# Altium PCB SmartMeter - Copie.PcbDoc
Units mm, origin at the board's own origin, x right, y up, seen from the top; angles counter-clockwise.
Board outline 36.42 x 43 mm, 2 copper layers (Top Layer, Bottom Layer), stack 0.071 mm thick; 33 components, 26 nets, 131 pads, 0 vias.
Unrouted connection lines stored in the file: 32.
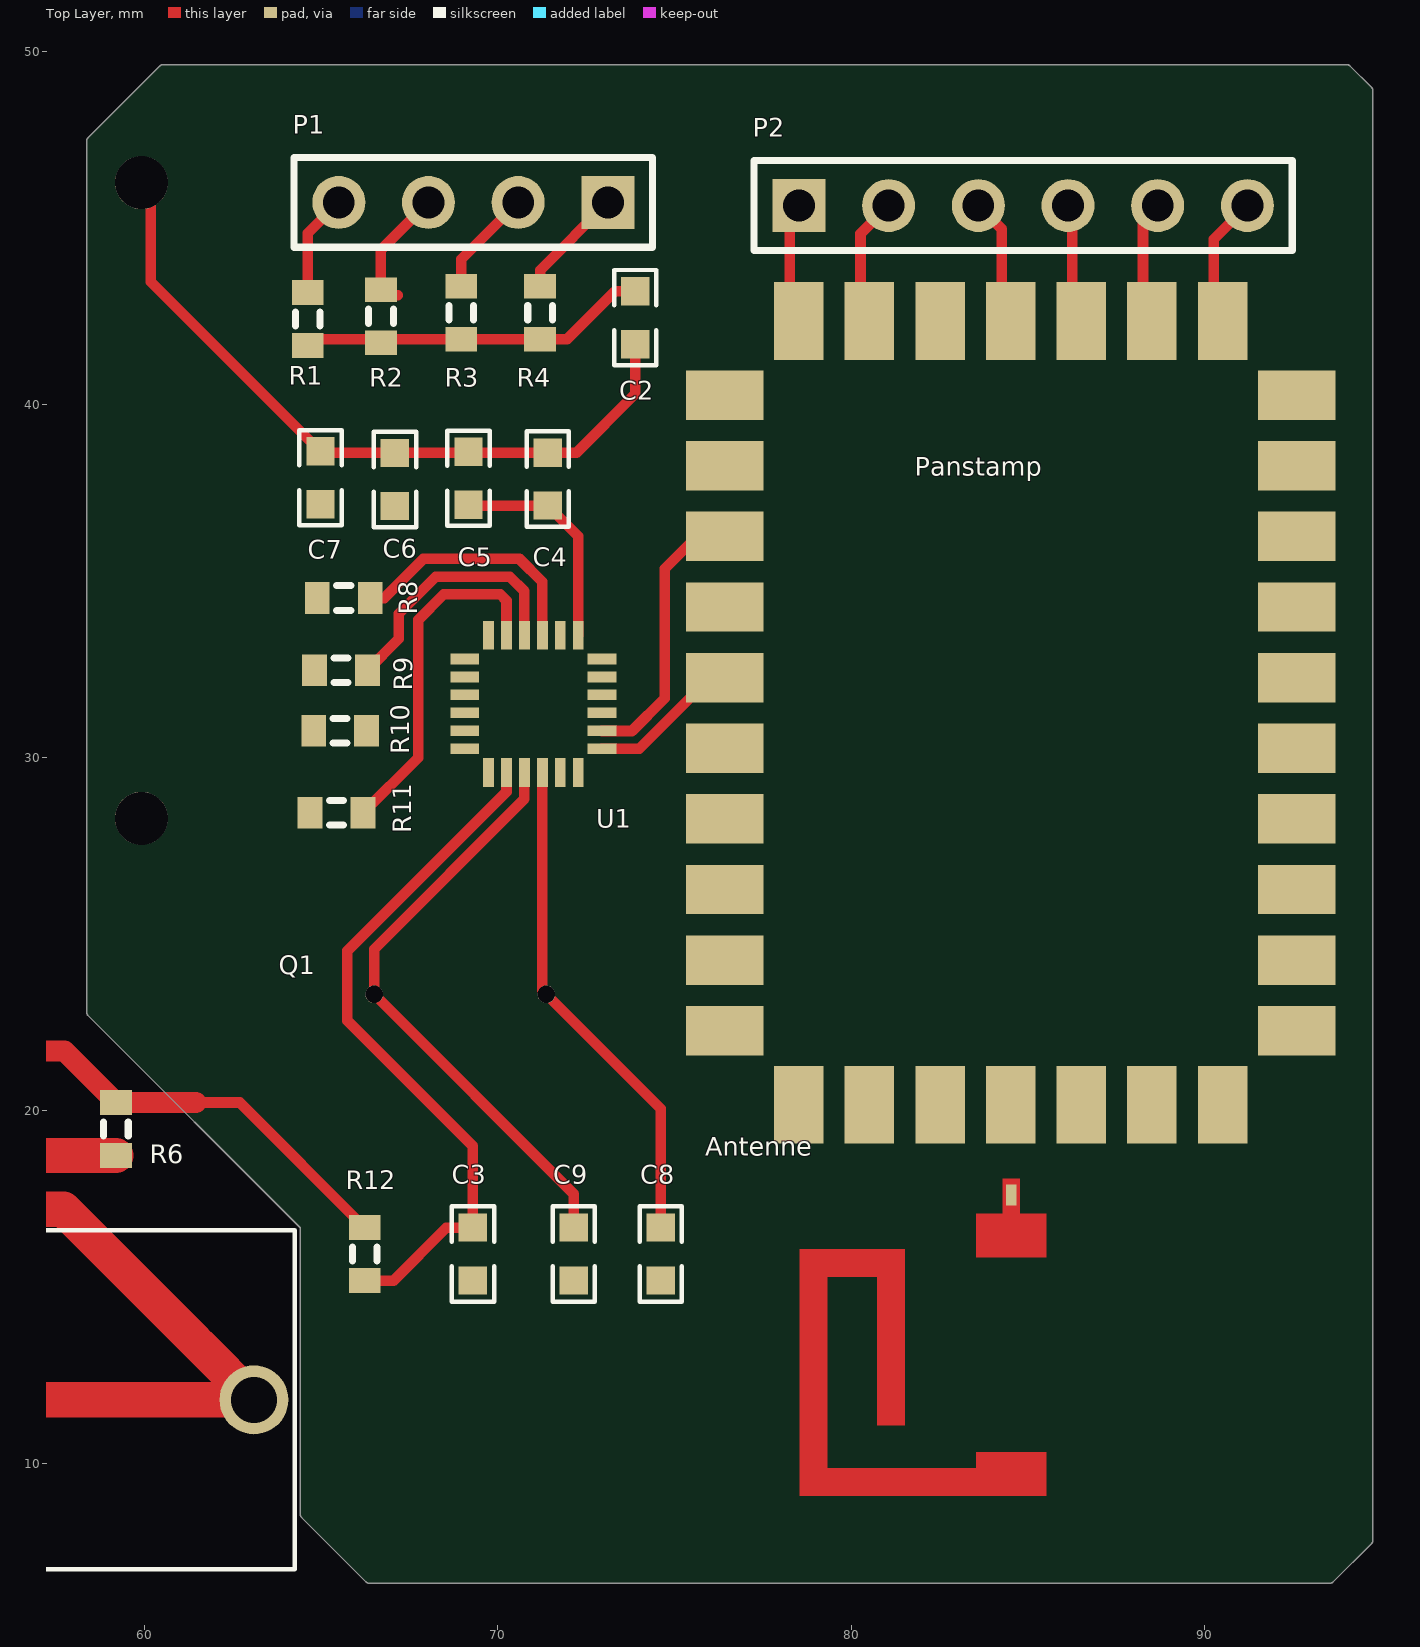
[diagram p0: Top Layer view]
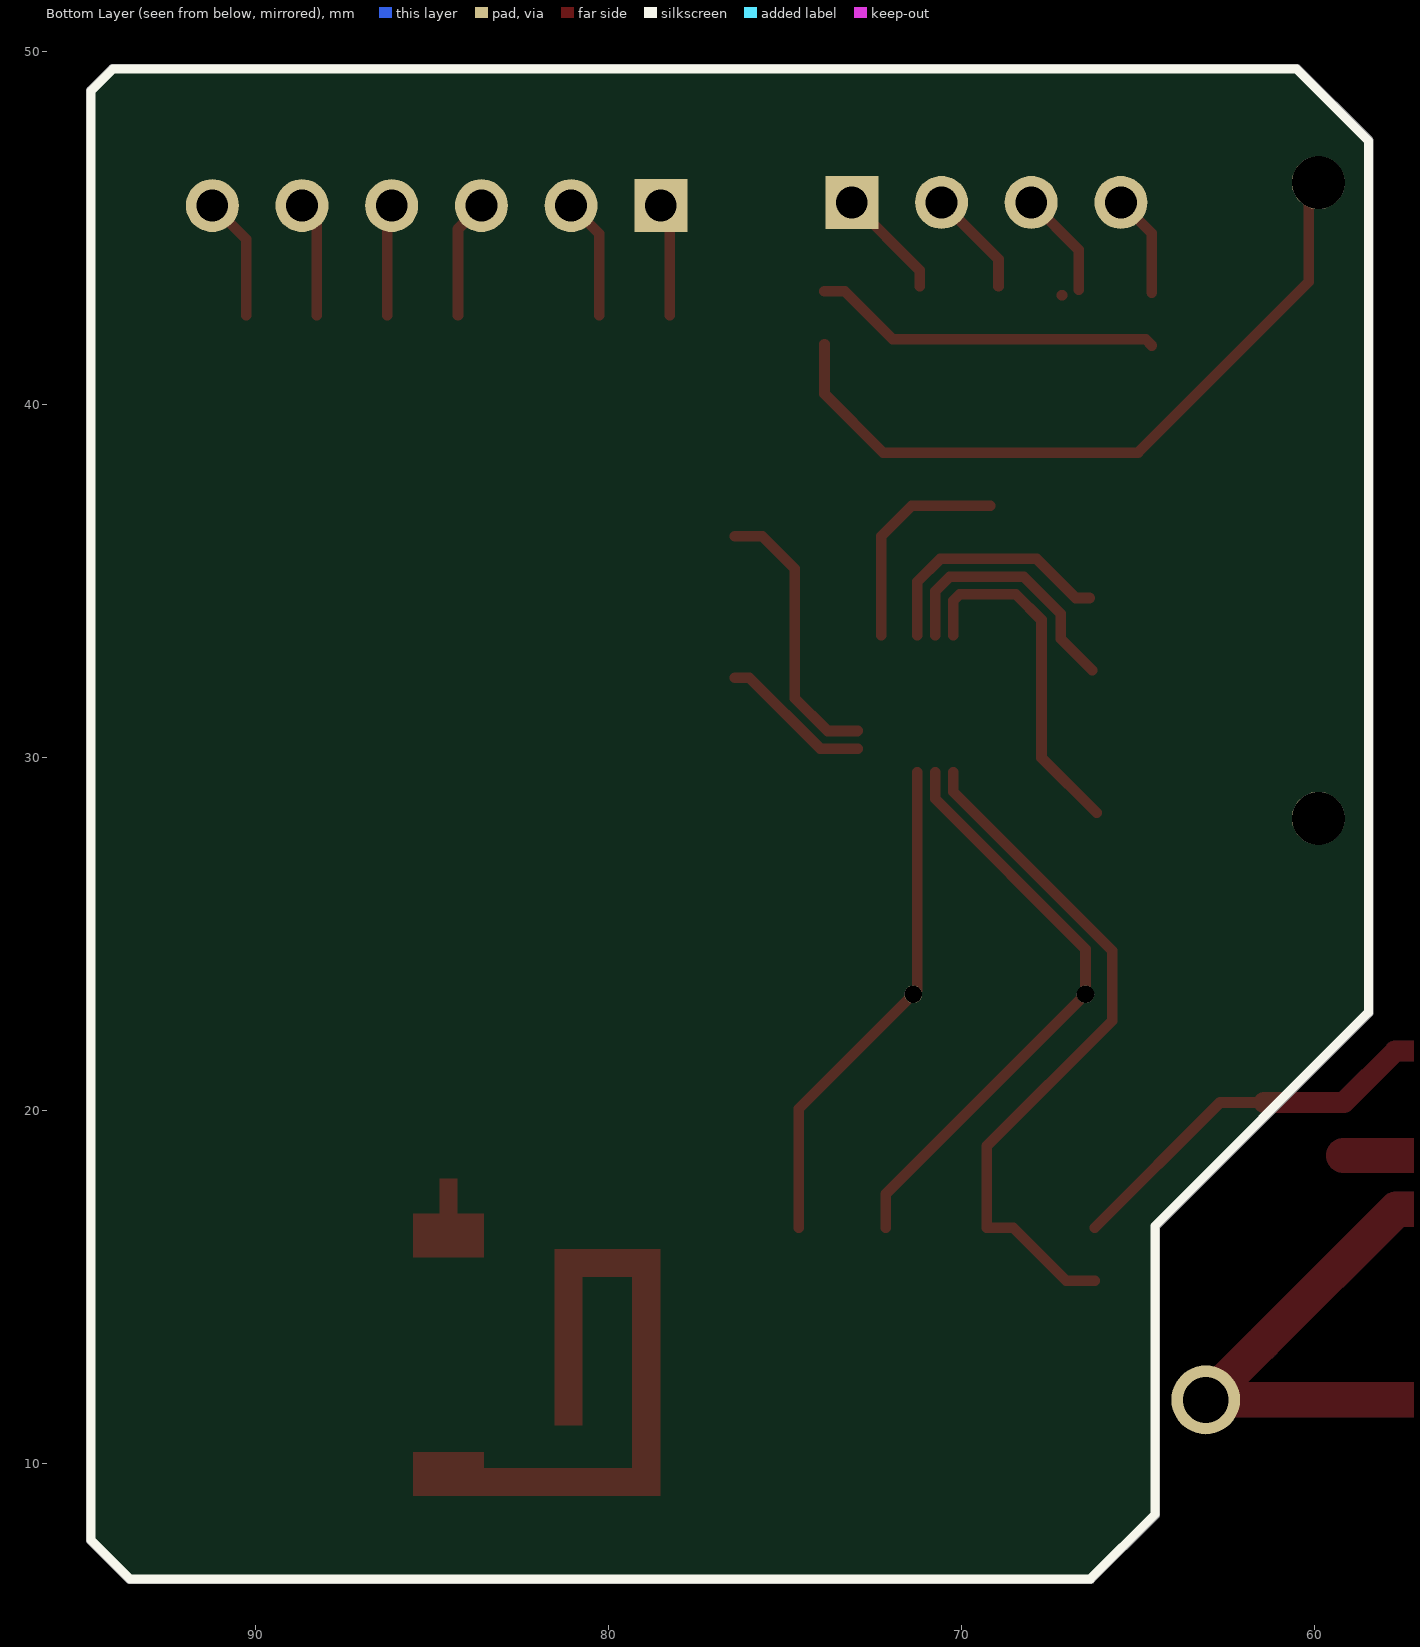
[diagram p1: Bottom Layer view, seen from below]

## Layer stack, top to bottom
Top Layer: signal copper 0.0356
Bottom Layer: signal copper 0.0356

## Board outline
58.393,22.694 64.401,16.686 64.401,8.572 ccw(c64.529,8.572) 64.439,8.482 66.267,6.654 ccw(c66.358,6.744) 66.358,6.616 93.561,6.616 ccw(c93.561,6.744) 93.651,6.654 94.743,7.746 94.743,7.745 ccw(c94.653,7.836) 94.78,7.836 94.78,48.882 ccw(c94.653,48.882) 94.743,48.973 94.743,48.972 94.134,49.582 ccw(c94.043,49.492) 94.043,49.619 60.515,49.619 ccw(c60.515,49.492) 60.425,49.582 58.393,47.55 58.394,47.55 ccw(c58.483,47.46) 58.356,47.46 58.356,22.784 ccw(c58.483,22.784)

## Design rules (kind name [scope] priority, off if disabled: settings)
Clearance Clearance_Max [InComponent('U1')] p1: gap=0.15
Clearance Clearance_INU [WithinRoom('INU')] p2: gap=0.2
Clearance [All] p3: gap=0.35
PolygonConnect [All] p1: connectstyle=Relief reliefconductorwidth=0.254 reliefentries=4 polygonreliefangle="90 Angle" airgapwidth=0.254
RoomDefinition INU [not IsComponent] p1: confinementstyle=ConfineIn formatcopy=TRUE lockcomponents=FALSE outline 65.786,13.373 76.772,13.373 76.772,48.476 65.786,48.476
RoutingVias [All] p1: holewidth=0.711 width=1.27 viastyle="Through Hole" minholewidth=0.711 minwidth=1.27 maxholewidth=0.711 maxwidth=1.27
SolderMaskExpansion [All] p1: expansion=0.102
UnpouredPolygon [All] p1: allowunpoured=FALSE
Width Width_INU [WithinRoom('INU')] p1: maxlimit=0.8 minlimit=0.2 preferedwidth=0.3 toplayer_maxwidth=0.4 minimp=50.000000 maximp=50.000000 favimp=50.000000
Width Width_HT [InNetClass('HT')] p2: maxlimit=3 minlimit=1 preferedwidth=2.184 minimp=50.000000 maximp=50.000000 favimp=50.000000
Width [All] p3: maxlimit=0.8 minlimit=0.3 preferedwidth=0.6 minimp=50.000000 maximp=50.000000 favimp=50.000000
29 further rules are at their usual default settings.

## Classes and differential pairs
net class HT: NetC1_1 NetC1_2 NetF1_1 NetR5_2 "NEUTRAL OUT"
component class "Components Class 1": U1
component class SmartMeter: C1 C2 C3 C4 C5 C6 C7 C8 C9 F1 P1 P2 Panstamp Q1 R1 R2 R3 R4 R5 R6 R7 R8 R9 R10 R11 R12 R13 Rshunt T1

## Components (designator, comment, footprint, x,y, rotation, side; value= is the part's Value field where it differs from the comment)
Antenne "Comment" PCBComponent_1#1 84.785,18.085 r180 top
C1 "100pF" "WCAP-CSGP 0603, H=0.8mm" 49.365,21.298 r90 top
C2 "100pF" "WCAP-CSGP 0603, H=0.8mm" 73.889,42.456 r90 top
C3 "100pF" "WCAP-CSGP 0603, H=0.8mm" 69.291,15.938 r270 top
C4 "1000pF" "WCAP-CSGP 0603, H=0.8mm" 71.412,37.884 r270 top
C5 "100pF" "WCAP-CSGP 0603, H=0.8mm" 69.164,37.91 r270 top
C6 "1uF" "WCAP-CSGP 0603, H=0.8mm" 67.081,37.871 r90 top
C7 "1uF" "WCAP-CSGP 0603, H=0.8mm" 64.973,37.922 r270 top
C8 "18pF" "WCAP-CSGP 0603, H=0.8mm" 74.612,15.938 r270 top
C9 "18pF" "WCAP-CSGP 0603, H=0.8mm" 72.149,15.938 r270 top
ENTREE "Comment" HDR1X2 48.578,18.263 r180 top
F1 "696103201002" 696103201002 51.841,11.811 r180 top
P1 "Header 4" HDR1X4 73.114,45.72 r180 top
P2 "Header 6" HDR1X6 78.524,45.631 r0 top
Panstamp "Panstamp" PCBComponent_1#2 92.621,22.263 r180 top
Q1 "Comment" PCBComponent_1#3 71.374,23.292 r180 top
R1 "Res3" J1-0603 64.618,42.418 r270 top
R2 "Res3" J1-0603 66.688,42.494 r270 top
R3 "Res3" J1-0603 68.961,42.596 r270 top
R4 "Res3" J1-0603 71.196,42.596 r270 top
R5 "Res3" J1-0603 55.829,17.958 r90 top
R6 "Res3" J1-0603 59.182,19.482 r90 top
R7 "Res3" J1-0603 55.842,22.441 r270 top
R8 "Res3" J1-0603 65.634,34.519 r0 top
R9 "Res3" J1-0603 65.557,32.474 r180 top
R10 "Res3" J1-0603 65.43,28.435 r180 top
R11 "Res3" J1-0603 65.532,30.759 r180 top
R12 "Res3" J1-0603 66.23,15.938 r90 top
R13 "Res3" J1-0603 52.019,19.774 r90 top
Rshunt "Res3" J1-0603 51.93,23.038 r90 top
SORITE "Comment" HDR1X2 42.481,20.866 r270 top
T1 "Alimentation 230AC/3.3DC" PCBComponent_1#4 42.405,46.279 r0 top
U1 "Maxim_78M6610+LMU" 21_0139I_T2444_4 71.006,31.521 r0 top

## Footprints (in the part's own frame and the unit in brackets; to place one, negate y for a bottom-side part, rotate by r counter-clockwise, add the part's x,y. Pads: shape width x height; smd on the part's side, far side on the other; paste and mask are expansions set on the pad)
21_0139I_T2444_4 [mil]
  rect 32x12 smd: 1(-76.5,50) 2(-76.5,30) 3(-76.5,10) 4(-76.5,-10) 5(-76.5,-30) 6(-76.5,-50) 13(76.5,-50) 14(76.5,-30) 15(76.5,-10) 16(76.5,10) 17(76.5,30) 18(76.5,50)
  rect 12x32 smd: 7(-50,-76.5) 8(-30,-76.5) 9(-10,-76.5) 10(10,-76.5) 11(30,-76.5) 12(50,-76.5) 19(50,76.5) 20(30,76.5) 21(10,76.5) 22(-10,76.5) 23(-30,76.5) 24(-50,76.5)
696103201002 [mm] "PCB - Clip Cover - THR"
  round 1.95 hole 1.3: 1(-11.25,0) 2(11.25,0)
  silkscreen extent -12.4,-4.8 12.4,4.8, body extent -12.4,-4.8 12.4,4.8, height 25
HDR1X2 [mm] "Connector; Header; 2 Position"
  rect 1.5x1.5 hole 0.9: 1(0,0)
  round 1.5 hole 0.9: 2(2.54,0)
  silkscreen extent -1.27,-1.27 3.81,1.27
HDR1X4 [mm] "Connector; Header; 4 Position"
  rect 1.5x1.5 hole 0.9: 1(0,0)
  round 1.5 hole 0.9: 2(2.54,0) 3(5.08,0) 4(7.62,0)
  silkscreen extent -1.27,-1.27 8.89,1.27
HDR1X6 [mm] "Connector; Header; 6 Position"
  rect 1.5x1.5 hole 0.9: 1(0,0)
  round 1.5 hole 0.9: 2(2.54,0) 3(5.08,0) 4(7.62,0) 5(10.16,0) 6(12.7,0)
  silkscreen extent -1.27,-1.27 13.97,1.27
J1-0603 [mm] "Chip Resistor, Body 1.6x0.8mm, IPC High Density"
  rect 0.7x0.9 smd: 1(-0.75,0) 2(0.75,0)
  silkscreen extent -0.2,-0.35 0.2,0.35, body extent -0.85,-0.48 0.85,0.48, height 0.9
PCBComponent_1#1 [mm]
  rect 0.3x0.6 smd: 0(0.245,0.47)
  Top Layer region: 0,0 0.5,0 0.5,1 0,1
  Top Layer region: -0.75,1 1.25,1 1.25,2.25 -0.75,2.25
  Top Layer region: -0.75,7.75 1.25,7.75 1.25,9 -0.75,9
  Top Layer region: 1.25,8.2 6.25,8.2 6.25,9 1.25,9
  Top Layer region: 5.45,2 6.25,2 6.25,9 5.45,9
  Top Layer region: 3.25,2 5.45,2 5.45,2.8 3.25,2.8
  Top Layer region: 3.25,2 4.05,2 4.05,7 3.25,7
PCBComponent_1#2 [mm]
  rect 2.2x1.4 smd: 1(0,0) 2(0,-1.999) 3(0,-4) 4(0,-6) 5(0,-8) 6(0,-10) 7(0,-12) 8(0,-14) 9(0,-16) 10(0,-18) 18(16.2,-18) 19(16.2,-16) 20(16.2,-14) 21(16.2,-12) 22(16.2,-10) 23(16.2,-8) 24(16.2,-6) 25(16.2,-4) 26(16.2,-2) 27(16.2,0)
  rect 1.4x2.2 smd: 11(2.1,-20.1) 12(4.1,-20.1) 13(6.1,-20.1) 14(8.1,-20.1) 15(10.1,-20.1) 16(12.1,-20.1) 17(14.1,-20.1) 28(14.1,2.1) 29(12.1,2.1) 30(10.1,2.1) 31(8.1,2.1) 32(6.1,2.1) 33(4.1,2.1) 34(2.1,2.1)
PCBComponent_1#3 [mm]
  round 0.5 hole 0.5: 1(0,0) 2(4.877,0)
PCBComponent_1#4 [mm]
  round 1.5 hole 1.5: 1(17.5,-18) 2(17.5,0) 3(0,0) 4(0,-19)
"WCAP-CSGP 0603, H=0.8mm" [mm] "MLCC 0603, H=0.8mm"
  rect 0.8x0.8 smd: 1(-0.75,0) 2(0.75,0)
  silkscreen extent -1.35,-0.6 1.35,0.6, body extent -0.8,-0.4 0.8,0.4, height 0.77

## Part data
C1 C2 C3 C4 C5 C6 C7 C8 C9: library part 0603C-1UF-10V-X5R-TDK, "CAPACITOR 0603 CERAMIC"
ENTREE SORITE: library part "Header 2"
F1: library part "WR-FSH, 696103201002", "WR-FSH Fuseholder THR Blocks PCB Clip Cover"
P1: "Header, 4-Pin"
P2: "Header, 6-Pin"
Panstamp: "Panstamp NRG 2.0"
Q1: library part Component_1
R1 R2 R3 R4 R5 R6 R7 R8 R9 R10 R11 R12 R13 Rshunt: "Resistor"
U1: library part "Maxim78M6610 + LMU", "Mesure d'énergie IC ENERGY MM PROCESSOR 24TQFN"

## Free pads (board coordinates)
  round 2 hole 1.5: 1(2.85,83.9) 2(92.15,83.9) 3(92.15,1.1) 4(2.85,1.1)

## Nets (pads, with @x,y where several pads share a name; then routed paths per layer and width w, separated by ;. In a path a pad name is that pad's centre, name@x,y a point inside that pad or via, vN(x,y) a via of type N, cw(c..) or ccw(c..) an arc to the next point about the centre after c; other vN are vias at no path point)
GND: C2.2 C3.2 C8.2 C9.2 Panstamp.28 Panstamp.29 Panstamp.30 Panstamp.32 Panstamp.33 Panstamp.34 R1.2 R2.2 R3.2 R4.2 T1.1 U1.2 U1.3 U1.5 U1.11 U1.17 | length 9.9
  Top Layer w0.3: R1.2 64.795,41.846 R3.2 R4.2 71.957,41.846 73.318,43.206 C2.2
NetC1_1: C1.1 F1.2 T1.3 | length 46.3
  Top Layer w1: F1.2 40.591,26.24 40.653,26.302 ; T1.3 40.653,44.526 40.653,26.302 ; C1.1 46.407,20.548 40.653,26.302
NetC1_2: C1.2 ENTREE.1 R10.2 R11.2 R13.2 Rshunt.1 T1.4 | length 17.6
  Top Layer w1: T1.4 47.636,22.048 C1.2 Rshunt.1@51.69,22.048 ; ENTREE.1 49.256,18.263 51.217,20.224 51.719,20.224 R13.2 51.93,20.613 Rshunt.1
NetC2_1: C2.1 C4.1 C5.1 C6.2 C7.1 R6.2 R7.2 R8.2 R11.1 R12.2 R13.1 T1.2 U1.21 | length 45.2
  Top Layer w0.3: T1.2 60.172,46.012 60.172,43.473 C7.1 65.011,38.634 C4.1 72.226,38.634 73.889,40.297 C2.1 ; 61.443,20.232 62.687,20.232 R12.2 ; R8.2 66.777,34.519 67.882,35.623 70.612,35.623 71.26,34.976 U1.21
  Top Layer w0.6: R13.1 53.175,19.024 R7.2 57.723,21.691 R6.2 61.443,20.232
NetC3_1: C3.1 R12.1 U1.8 U1.18 | length 19.9
  Top Layer w0.3: R12.1 67.042,15.188 68.543,16.688 C3.1 69.291,18.999 65.739,22.551 65.739,24.524 70.244,29.028 U1.8
NetC4_2: C4.2 C5.2 R7.1 U1.19 | length 6.2
  Top Layer w0.3: C5.2@69.19,37.134 C4.2 72.276,36.27 U1.19
NetC6_1: C6.1 R9.1 U1.22 | length 7.4
  Top Layer w0.3: R9.1 67.196,33.362 67.196,34.074 68.245,35.124 70.337,35.124 70.752,34.709 U1.22
NetC7_2: C7.2 R10.1 U1.23 | length 10
  Top Layer w0.3: R10.1 67.742,29.997 67.742,33.896 68.469,34.624 70.063,34.624 70.244,34.442 U1.23
NetC8_1: C8.1 Q1.1 U1.10 | length 14.3
  Top Layer w0.3: U1.10 71.26,23.406 Q1.1 74.612,20.053 C8.1
NetC9_1: C9.1 Q1.2 U1.9 | length 17
  Top Layer w0.3: U1.9 70.752,28.829 66.497,24.575 Q1.2 72.149,17.64 C9.1
NetF1_1: ENTREE.2 F1.1 R5.1 SORITE.2 | length 32.9
  Top Layer w0.3: 61.443,13.46 61.529,13.373
  Top Layer w1: SORITE.2 42.545,18.263 ENTREE.2 46.038,18.101 52.327,11.811 F1.1 61.529,13.373 ; R5.1 57.695,17.208 61.443,13.46
NetP1_1: P1.1 R4.1 U1.16 | length 3.2
  Top Layer w0.3: R4.1 71.196,43.802 P1.1
NetP1_2: P1.2 R3.1 U1.4 | length 3
  Top Layer w0.3: R3.1 68.961,44.107 P1.2
NetP1_3: P1.3 R2.1 U1.7 | length 3
  Top Layer w0.3: R2.1 66.688,44.374 P1.3 ; 67.158,43.092 67.165,43.092
NetP1_4: P1.4 R1.1 U1.15 | length 2.9
  Top Layer w0.3: R1.1 64.618,44.844 P1.4
NetP2_1: P2.1 Panstamp.17 | length 2.8
  Top Layer w0.3: Panstamp.17@78.267,42.528 P2.1@78.267,45.374
NetP2_2: P2.2 Panstamp.16 | length 3.4
  Top Layer w0.3: Panstamp.16@80.267,42.528 80.267,44.834 P2.2
NetP2_3: P2.3 Panstamp.14 | length 3.4
  Top Layer w0.3: P2.3 84.267,44.968 Panstamp.14@84.267,42.528
NetP2_4: P2.4 Panstamp.13 | length 3.2
  Top Layer w0.3: P2.4 86.267,45.508 Panstamp.13@86.267,42.528
NetP2_5: P2.5 Panstamp.12 | length 3.3
  Top Layer w0.3: Panstamp.12@88.267,42.528 88.267,45.214 P2.5
NetP2_6: P2.6 Panstamp.11 | length 3.5
  Top Layer w0.3: Panstamp.11@90.267,42.528 90.267,44.674 P2.6
NetPanstamp_20: Panstamp.20 U1.14 | length 7.9
  Top Layer w0.3: U1.14 72.957,30.751 73.796,30.751 74.727,31.682 74.727,35.344 75.646,36.263 Panstamp.20
NetPanstamp_22: Panstamp.22 U1.13 | length 4.3
  Top Layer w0.3: U1.13 74.003,30.251 76.015,32.263 Panstamp.22
NetPanstamp_23: Panstamp.23 U1.6
NetR5_2: R5.2 R6.1 | length 3.4
  Top Layer w1: R5.2 55.853,18.732 R6.1
"NEUTRAL OUT": R8.1 R9.2 Rshunt.2 SORITE.1
pads on no net: Antenne.0 Panstamp.1 Panstamp.2 Panstamp.3 Panstamp.4 Panstamp.5 Panstamp.6 Panstamp.7 Panstamp.8 Panstamp.9 Panstamp.10 Panstamp.15 Panstamp.18 Panstamp.19 Panstamp.21 Panstamp.24 Panstamp.25 Panstamp.26 Panstamp.27 Panstamp.31 U1.1 U1.12 U1.20 U1.24

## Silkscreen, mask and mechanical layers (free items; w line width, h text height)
Bottom Overlay:
  lines w0.254: 93.548,6.744 93.561,6.744 ; 93.561,6.744 66.358,6.744 64.529,8.572 64.529,16.739 58.483,22.784 58.483,47.46 60.515,49.492 94.043,49.492 94.653,48.882 94.653,7.836 93.561,6.744
Mechanical 1:
  lines w0.254: 0,-0.749 95,-0.749 95,85.979 0,85.979 0,-0.749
